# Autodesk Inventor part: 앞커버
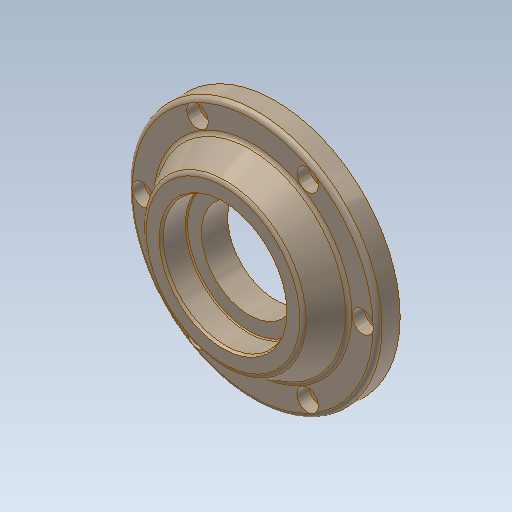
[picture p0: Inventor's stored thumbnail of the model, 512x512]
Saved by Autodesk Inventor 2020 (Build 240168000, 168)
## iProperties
Created: 2013-01
Part Number: 앞커버
Document SubType Name: Modeling
Designer: 한국산업디자인학원[gmhk.co.kr]
Density: 2.71 g/cm^3
Material: 알루미늄 6061
Mass: 321.536 g
Surface Area: 281.944 cm^2
Volume: 118.648 cm^3
Appearance: 알루미늄 - 평지(2)
Author: 한국산업디자인학원[gmhk.co.kr]
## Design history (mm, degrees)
sketch "스케치2"
  geometry: L1 (-55, 0)-(55, 0) reference; L2 (35.98, -6)-(-35.98, -6) reference; L3 (-42.5, -25)-(-42.5, 0) reference; L4 (-37, -6)-(-37, 0); L5 (-55, 0)-(-55, 10); L6 (-55, 10)-(-42.5, 10); L7 (-37, -6)-(-42.5, -6); L8 (-42.5, 10)-(-34.994, 23); L9 (-34.994, 23)-(0, 23); L10 (-55, 0)-(-42.5, 0); L11 (-42.5, -6)-(-42.5, 0); L12 (0, 0)-(0, 23); L13 (0, 0)-(-37, 0)
  constraints: 22 end point, 4 perpendicular, 3 collinear, 2 parallel, 2 point on line, 1 vertical, 2 other
  dimensions: "d2" = 10 distance of L1.start L5.end; "d4" = 120 deg angle of L8 L6; "d5" = 13 distance between parallel lines of L6 L9; "d6" = 74 diameter of L4 L12; "d7" = 85 diameter of L6.end L12
revolve "회전1" sketch "스케치2" stored, may be unused: angle "d8" = 90 deg
fillet "모깎기1" dims "d9" = 2
sketch "스케치3"
  geometry: C1 r 2.067 at (48.5, 0) reference; 1 further point
hole "구멍1" sketch "스케치3" at (48.5, 0) diameter "d10" = 5.5; stored, may be unused: countersink angle "d14" = 90 deg, drill point angle "d16" = 118 deg; dims "d11" = 6, "d12" = 9.5, "d13" = 5.4, "d15" = 8
fillet "모깎기2" dims "d20" = 3
chamfer "모따기1" distance "d21" = 1; stored, may be unused: second distance "d22" = 2, angle "d23" = 45 deg
sketch "스케치4"
  geometry: L1 (-33.84, 23)-(33.84, 23) reference; L2 (34, 0)-(-34, 0) reference; L3 (0, 0)-(0, 23); L4 (27.5, 21.9)-(27.5, 12.1); L5 (27, 11.6)-(21, 11.6); L6 (21, 11.6)-(21, 0); L7 (27.5, 21.9)-(28.135, 23); A1 r 0.5 centre (27, 12.1) between (27, 11.6) and (27.5, 12.1)
  constraints: 10 end point, 2 perpendicular, 2 point on circle, 2 point on line, 2 tangent, 1 centre point, 1 midpoint, 1 parallel
  dimensions: "d24" = 11.4 distance between parallel lines of L5 L1; "d25" = 1.1 distance from line of L4.start L1; "d26" = 30 deg angle of L7 L4; "d27" = 0.5 radius of A1; "d28" = 55 diameter of L4 L3; "d29" = 42 diameter of L6 L3
revolve "회전2" sketch "스케치4" stored, may be unused: angle "d30" = 90 deg
node "솔리드1"
pattern_circular "원형 패턴1" dims angle "d18" = 360 deg
node "참조1"
node "참조2"
node "참조3"
